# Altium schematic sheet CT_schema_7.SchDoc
size 146 x 119 mm
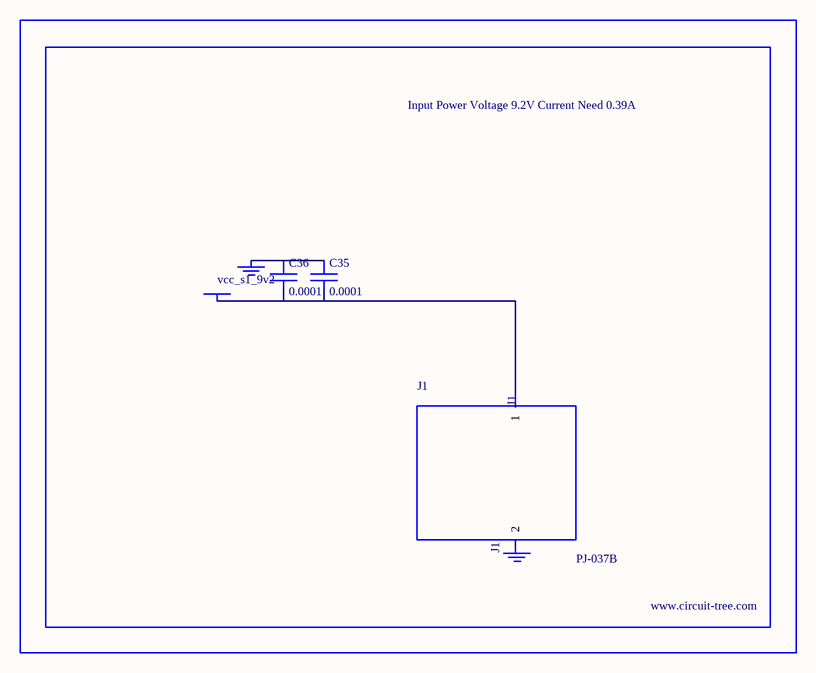
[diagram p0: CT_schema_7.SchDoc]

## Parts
BORDER6  (no value)
C35  0.0001  [EXV-9H]
C36  0.0001  [EXV-9H]
GND_INSTANCE_6_0  (no value)
GND_INSTANCE_6_1  (no value)
J1  PJ-037B  [PJ-037B_PACKAGE]
POWER_INSTANCE_6_0  vcc_s1_9v2

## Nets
NetC35_1: C35.1 C36.1 GND_INSTANCE_6_0.0(GND)
NetC35_2: C35.2 C36.2 J1.1 POWER_INSTANCE_6_0.0(PWR)

Not connected (* = marked no-connect by the designer): GND_INSTANCE_6_1 0(GND); J1 2

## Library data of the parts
BORDER6 = BORDER_PAGE6
C35 C36 = EDK107M035A9HAA
GND_INSTANCE_6_0 GND_INSTANCE_6_1 = GND
POWER_INSTANCE_6_0 = PWR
